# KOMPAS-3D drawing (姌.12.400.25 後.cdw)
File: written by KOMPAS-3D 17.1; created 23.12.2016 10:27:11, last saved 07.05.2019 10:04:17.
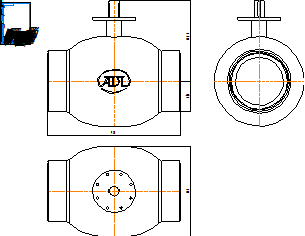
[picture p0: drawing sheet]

Sheet 1: A4, portrait

Title block, sheet 1: name: КШ.12.400.25 сс; material: Внимание! Данный продукт является объектом авторского права ООО «Торговый Дом АДЛ». / Запрещается изменение, копирование, распространение / (в том числе путем копирования на другие сайты и ресурсы в Интернете) / или любое иное использование информации и объектов без предварительного / согласия правообладателя (ООО «Торговый Дом АДЛ»).; sheets: 1; organisation: ООО "Торговый дом АДЛ"; sheet format: A4; stored path: C:\Users\tra\Desktop\2д чертежи\Шаровые краны БИВАЛ\КШ_Бивал_серия_11_12\KOMPAS_2D\КШ.12.400.25 сс.cdw

Views: Вид 1, Проекционный вид 2, Проекционный вид 3
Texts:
  Klimkovich
  ADL
Dimensions and other numbers on the sheet: 930; 564,5; 213; 630; 1:1; 1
